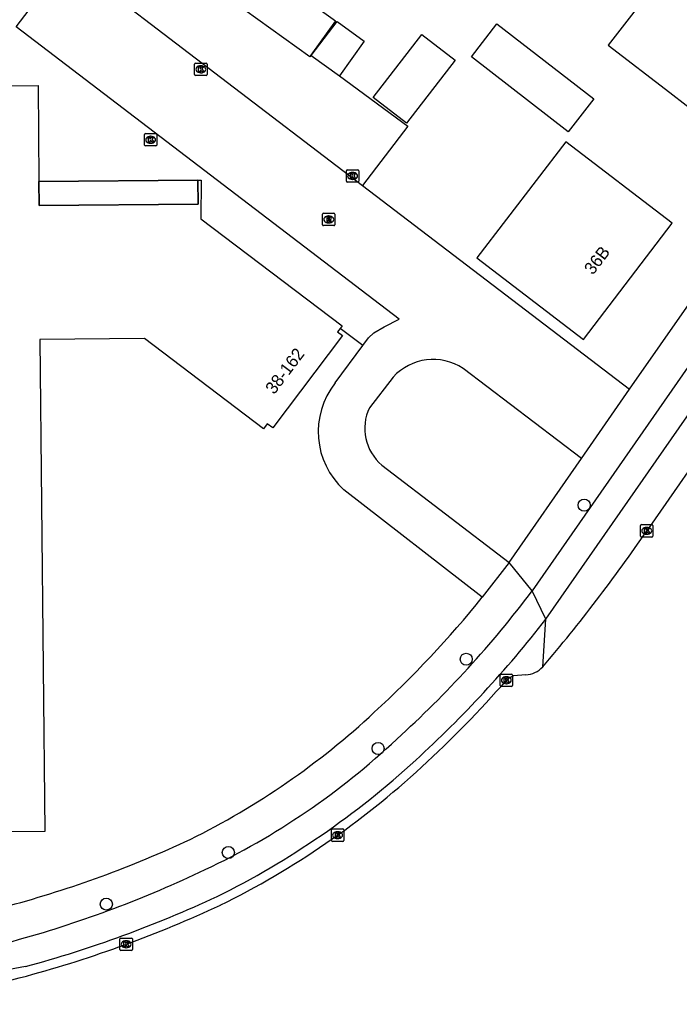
# Model space of a CAD drawing. Extents: x 160158 to 160921, y 381517 to 382041.
# Drawn here: x 160584.1 to 160637.4, y 381547.2 to 381626.4 of the extents above; entities that cross this region are included whole.
import ezdxf

# ---------------------------------------------------------------- set-up
doc = ezdxf.new("R2010")
doc.units = 0
for name, color, linetype in [('IMGEO_Berm_open', 7, 'Continuous'), ('IMGEO_Boom', 7, 'Continuous'), ('IMGEO_Fietspad_open', 7, 'Continuous'), ('IMGEO_Kolk', 7, 'Continuous'), ('IMGEO_Pand', 7, 'Continuous'), ('IMGEO_Pand_nummerreeks', 7, 'Continuous'), ('IMGEO_Pand_overbouw', 7, 'Continuous'), ('IMGEO_Parkeervlak_open', 7, 'Continuous'), ('IMGEO_Rijbaan_lokaal_gesloten', 7, 'Continuous'), ('IMGEO_Rijbaan_lokaal_open', 7, 'Continuous'), ('IMGEO_Rioolput', 7, 'Continuous'), ('IMGEO_Voetpad_open', 7, 'Continuous')]:
    doc.layers.add(name, color=color, linetype=linetype)

msp = doc.modelspace()

# ---------------------------------------------------------------- linework, layer by layer
at = {"layer": 'IMGEO_Berm_open'}
msp.add_lwpolyline([(160626.346, 381574.092), (160626.609, 381577.958)], dxfattribs=at)
at = {"layer": 'IMGEO_Boom'}
for centre in [(160629.691, 381587.166), (160620.166, 381574.712), (160613.04, 381567.494), (160600.942, 381559.087), (160591.077, 381554.92)]:
    msp.add_circle(centre, 0.489, dxfattribs=at)
at = {"layer": 'IMGEO_Fietspad_open'}
for points in [[(160658.078, 381626.982), (160657.224, 381625.75), (160654.545, 381621.952), (160652.131, 381618.546), (160625.5, 381580.252)], [(160626.609, 381577.958), (160653.548, 381616.624), (160658.001, 381622.958)], [(160626.609, 381577.958), (160625.5, 381580.252)], [(160584.546, 381549.868), (160573.856, 381547.875), (160569.741, 381547.684)]]:
    msp.add_lwpolyline(points, dxfattribs=at)
for centre, radius, start, end in [((160558.076, 381630.831), 84.287, 312.06612, 323.12406), ((160554.773, 381633.721), 90.939, 312.39102, 322.17935), ((160573.524, 381611.804), 59.825, 295.27447, 313.29148), ((160568.779, 381618.18), 70.019, 296.5051, 312.49983), ((160559.234, 381641.019), 92.346, 285.6024, 295.55323), ((160558.323, 381645.705), 99.36, 285.30275, 294.81732), ((160569.083, 381603.441), 53.507, 273.98019, 286.26704)]:
    msp.add_arc(centre, radius, start, end, dxfattribs=at)
at = {"layer": 'IMGEO_Kolk'}
for p, q in [((160598.215, 381621.98), (160598.215, 381622.832)), ((160598.29, 381622.906), (160599.142, 381622.906)), ((160599.216, 381622.832), (160599.216, 381621.98)), ((160598.726, 381622.126), (160598.701, 381622.126)), ((160598.703, 381622.686), (160598.728, 381622.686)), ((160599.142, 381621.906), (160598.29, 381621.906)), ((160594.161, 381616.286), (160594.161, 381617.138)), ((160594.236, 381617.212), (160595.088, 381617.212)), ((160594.649, 381616.992), (160594.674, 381616.992)), ((160595.162, 381617.138), (160595.162, 381616.286)), ((160595.088, 381616.212), (160594.236, 381616.212)), ((160594.672, 381616.432), (160594.647, 381616.432)), ((160610.479, 381613.358), (160610.479, 381614.21)), ((160610.554, 381614.284), (160611.406, 381614.284)), ((160611.48, 381614.21), (160611.48, 381613.358)), ((160610.99, 381613.504), (160610.965, 381613.504)), ((160610.967, 381614.064), (160610.992, 381614.064)), ((160611.406, 381613.284), (160610.554, 381613.284)), ((160634.325, 381585.596), (160635.177, 381585.596)), ((160634.25, 381584.67), (160634.25, 381585.522)), ((160634.761, 381584.816), (160634.736, 381584.816)), ((160634.738, 381585.376), (160634.763, 381585.376)), ((160635.251, 381585.522), (160635.251, 381584.67)), ((160635.177, 381584.596), (160634.325, 381584.596)), ((160622.906, 381572.585), (160622.906, 381573.437)), ((160622.981, 381573.511), (160623.833, 381573.511)), ((160623.394, 381573.291), (160623.419, 381573.291)), ((160623.907, 381573.437), (160623.907, 381572.585)), ((160623.833, 381572.511), (160622.981, 381572.511)), ((160623.417, 381572.731), (160623.392, 381572.731)), ((160609.27, 381560.066), (160609.27, 381560.918)), ((160609.345, 381560.992), (160610.197, 381560.992)), ((160609.758, 381560.772), (160609.783, 381560.772)), ((160610.271, 381560.918), (160610.271, 381560.066)), ((160610.197, 381559.992), (160609.345, 381559.992)), ((160609.781, 381560.212), (160609.756, 381560.212)), ((160592.183, 381551.246), (160592.183, 381552.098)), ((160592.258, 381552.172), (160593.11, 381552.172)), ((160592.671, 381551.952), (160592.696, 381551.952)), ((160593.184, 381552.098), (160593.184, 381551.246)), ((160593.11, 381551.172), (160592.258, 381551.172)), ((160592.694, 381551.392), (160592.669, 381551.392))]:
    msp.add_line(p, q, dxfattribs=at)
for points in [[(160598.215, 381621.98), (160598.215, 381622.832)], [(160598.29, 381622.906), (160599.142, 381622.906)], [(160599.216, 381622.832), (160599.216, 381621.98)], [(160598.536, 381622.606), (160598.659, 381622.606), (160598.659, 381622.455), (160598.789, 381622.606), (160598.953, 381622.606), (160598.807, 381622.455), (160598.96, 381622.206), (160598.808, 381622.206), (160598.723, 381622.37), (160598.659, 381622.303), (160598.659, 381622.206), (160598.536, 381622.206), (160598.536, 381622.606)], [(160599.142, 381621.906), (160598.29, 381621.906)], [(160594.161, 381616.286), (160594.161, 381617.138)], [(160594.236, 381617.212), (160595.088, 381617.212)], [(160594.482, 381616.912), (160594.605, 381616.912), (160594.605, 381616.761), (160594.735, 381616.912), (160594.899, 381616.912), (160594.753, 381616.761), (160594.906, 381616.512), (160594.754, 381616.512), (160594.669, 381616.676), (160594.605, 381616.609), (160594.605, 381616.512), (160594.482, 381616.512), (160594.482, 381616.912)], [(160595.162, 381617.138), (160595.162, 381616.286)], [(160595.088, 381616.212), (160594.236, 381616.212)], [(160610.479, 381613.358), (160610.479, 381614.21)], [(160610.554, 381614.284), (160611.406, 381614.284)], [(160611.48, 381614.21), (160611.48, 381613.358)], [(160610.8, 381613.984), (160610.923, 381613.984), (160610.923, 381613.833), (160611.053, 381613.984), (160611.217, 381613.984), (160611.071, 381613.833), (160611.224, 381613.584), (160611.072, 381613.584), (160610.987, 381613.748), (160610.923, 381613.681), (160610.923, 381613.584), (160610.8, 381613.584), (160610.8, 381613.984)], [(160611.406, 381613.284), (160610.554, 381613.284)], [(160634.325, 381585.596), (160635.177, 381585.596)], [(160634.25, 381584.67), (160634.25, 381585.522)], [(160634.571, 381585.296), (160634.694, 381585.296), (160634.694, 381585.145), (160634.824, 381585.296), (160634.988, 381585.296), (160634.842, 381585.145), (160634.995, 381584.896), (160634.843, 381584.896), (160634.758, 381585.06), (160634.694, 381584.993), (160634.694, 381584.896), (160634.571, 381584.896), (160634.571, 381585.296)], [(160635.251, 381585.522), (160635.251, 381584.67)], [(160635.177, 381584.596), (160634.325, 381584.596)], [(160622.906, 381572.585), (160622.906, 381573.437)], [(160622.981, 381573.511), (160623.833, 381573.511)], [(160623.227, 381573.211), (160623.35, 381573.211), (160623.35, 381573.06), (160623.48, 381573.211), (160623.644, 381573.211), (160623.498, 381573.06), (160623.651, 381572.811), (160623.499, 381572.811), (160623.414, 381572.975), (160623.35, 381572.908), (160623.35, 381572.811), (160623.227, 381572.811), (160623.227, 381573.211)], [(160623.907, 381573.437), (160623.907, 381572.585)], [(160623.833, 381572.511), (160622.981, 381572.511)], [(160609.27, 381560.066), (160609.27, 381560.918)], [(160609.345, 381560.992), (160610.197, 381560.992)], [(160609.591, 381560.692), (160609.714, 381560.692), (160609.714, 381560.541), (160609.844, 381560.692), (160610.008, 381560.692), (160609.862, 381560.541), (160610.015, 381560.292), (160609.863, 381560.292), (160609.778, 381560.456), (160609.714, 381560.389), (160609.714, 381560.292), (160609.591, 381560.292), (160609.591, 381560.692)], [(160610.271, 381560.918), (160610.271, 381560.066)], [(160610.197, 381559.992), (160609.345, 381559.992)], [(160592.183, 381551.246), (160592.183, 381552.098)], [(160592.258, 381552.172), (160593.11, 381552.172)], [(160592.504, 381551.872), (160592.627, 381551.872), (160592.627, 381551.721), (160592.757, 381551.872), (160592.921, 381551.872), (160592.775, 381551.721), (160592.928, 381551.472), (160592.776, 381551.472), (160592.691, 381551.636), (160592.627, 381551.569), (160592.627, 381551.472), (160592.504, 381551.472), (160592.504, 381551.872)], [(160593.184, 381552.098), (160593.184, 381551.246)], [(160593.11, 381551.172), (160592.258, 381551.172)]]:
    msp.add_lwpolyline(points, dxfattribs=at)
for centre, start, end in [((160598.292, 381622.83), 91.55205, 178.44795), ((160598.292, 381622.83), 91.55205, 178.44795), ((160599.14, 381622.83), 1.55205, 88.44795), ((160599.14, 381622.83), 1.55205, 88.44795), ((160598.292, 381621.982), 181.55205, 268.44795), ((160598.292, 381621.982), 181.55205, 268.44795), ((160599.14, 381621.982), 271.55205, 358.44795), ((160599.14, 381621.982), 271.55205, 358.44795), ((160594.238, 381617.136), 91.55205, 178.44795), ((160594.238, 381617.136), 91.55205, 178.44795), ((160595.086, 381617.136), 1.55205, 88.44795), ((160595.086, 381617.136), 1.55205, 88.44795), ((160594.238, 381616.288), 181.55205, 268.44795), ((160594.238, 381616.288), 181.55205, 268.44795), ((160595.086, 381616.288), 271.55205, 358.44795), ((160595.086, 381616.288), 271.55205, 358.44795), ((160610.556, 381614.208), 91.55205, 178.44795), ((160610.556, 381614.208), 91.55205, 178.44795), ((160611.404, 381614.208), 1.55205, 88.44795), ((160611.404, 381614.208), 1.55205, 88.44795), ((160610.556, 381613.36), 181.55205, 268.44795), ((160610.556, 381613.36), 181.55205, 268.44795), ((160611.404, 381613.36), 271.55205, 358.44795), ((160611.404, 381613.36), 271.55205, 358.44795), ((160634.327, 381585.52), 91.55205, 178.44795), ((160634.327, 381585.52), 91.55205, 178.44795), ((160635.175, 381585.52), 1.55205, 88.44795), ((160635.175, 381585.52), 1.55205, 88.44795), ((160634.327, 381584.672), 181.55205, 268.44795), ((160634.327, 381584.672), 181.55205, 268.44795), ((160635.175, 381584.672), 271.55205, 358.44795), ((160635.175, 381584.672), 271.55205, 358.44795), ((160622.983, 381573.435), 91.55205, 178.44795), ((160622.983, 381573.435), 91.55205, 178.44795), ((160623.831, 381573.435), 1.55205, 88.44795), ((160623.831, 381573.435), 1.55205, 88.44795), ((160622.983, 381572.587), 181.55205, 268.44795), ((160622.983, 381572.587), 181.55205, 268.44795), ((160623.831, 381572.587), 271.55205, 358.44795), ((160623.831, 381572.587), 271.55205, 358.44795), ((160609.347, 381560.916), 91.55205, 178.44795), ((160609.347, 381560.916), 91.55205, 178.44795), ((160610.195, 381560.916), 1.55205, 88.44795), ((160610.195, 381560.916), 1.55205, 88.44795), ((160609.347, 381560.068), 181.55205, 268.44795), ((160609.347, 381560.068), 181.55205, 268.44795), ((160610.195, 381560.068), 271.55205, 358.44795), ((160610.195, 381560.068), 271.55205, 358.44795), ((160592.26, 381552.096), 91.55205, 178.44795), ((160592.26, 381552.096), 91.55205, 178.44795), ((160593.108, 381552.096), 1.55205, 88.44795), ((160593.108, 381552.096), 1.55205, 88.44795), ((160592.26, 381551.248), 181.55205, 268.44795), ((160592.26, 381551.248), 181.55205, 268.44795), ((160593.108, 381551.248), 271.55205, 358.44795), ((160593.108, 381551.248), 271.55205, 358.44795)]:
    msp.add_arc(centre, 0.0765, start, end, dxfattribs=at)
for centre, major_axis, ratio, start_param, end_param in [((160598.702, 381622.406), (-0.387, 0.002), 0.722429, 4.712389, 7.853982), ((160598.727, 381622.406), (-0.39, 0.002), 0.717154, 1.570796, 4.712389), ((160594.648, 381616.712), (-0.387, 0.002), 0.722429, 4.712389, 7.853982), ((160594.673, 381616.712), (-0.39, 0.002), 0.717154, 1.570796, 4.712389), ((160610.966, 381613.784), (-0.387, 0.002), 0.722429, 4.712389, 7.853982), ((160610.991, 381613.784), (-0.39, 0.002), 0.717154, 1.570796, 4.712389), ((160634.737, 381585.096), (-0.387, 0.002), 0.722429, 4.712389, 7.853982), ((160634.762, 381585.096), (-0.39, 0.002), 0.717154, 1.570796, 4.712389), ((160623.393, 381573.011), (-0.387, 0.002), 0.722429, 4.712389, 7.853982), ((160623.418, 381573.011), (-0.39, 0.002), 0.717154, 1.570796, 4.712389), ((160609.757, 381560.492), (-0.387, 0.002), 0.722429, 4.712389, 7.853982), ((160609.782, 381560.492), (-0.39, 0.002), 0.717154, 1.570796, 4.712389), ((160592.67, 381551.672), (-0.387, 0.002), 0.722429, 4.712389, 7.853982), ((160592.695, 381551.672), (-0.39, 0.002), 0.717154, 1.570796, 4.712389)]:
    msp.add_ellipse(centre, major_axis=major_axis, ratio=ratio, start_param=start_param, end_param=end_param, dxfattribs=at)
at = {"layer": 'IMGEO_Pand'}
for points in [[(160636.053, 381630.085), (160631.637, 381624.368), (160636.619, 381620.52), (160640.576, 381617.464), (160647.232, 381626.081), (160639.436, 381632.103)], [(160604.359, 381630.089), (160609.609, 381626.314), (160607.615, 381623.541)], [(160607.615, 381623.541), (160607.526, 381623.417), (160602.276, 381627.192), (160602.357, 381627.305)], [(160607.624, 381623.535), (160609.734, 381626.268), (160611.928, 381624.691), (160609.914, 381621.889)], [(160630.465, 381620.012), (160628.398, 381617.346), (160620.579, 381623.406), (160622.646, 381626.072), (160630.465, 381620.012)], [(160619.261, 381623.147), (160615.325, 381618.052), (160612.65, 381620.118), (160616.585, 381625.214), (160619.261, 381623.147)], [(160607.624, 381623.535), (160609.914, 381621.889)], [(160609.979, 381601.448), (160609.769, 381601.17), (160610.162, 381600.874), (160604.524, 381593.418), (160604.088, 381593.748), (160603.785, 381593.347), (160594.153, 381600.631), (160585.715, 381600.557), (160586.116, 381560.796), (160572.564, 381560.678), (160572.228, 381599.143), (160573.491, 381599.154), (160573.451, 381603.696), (160552.72, 381603.514), (160552.569, 381620.809), (160576.509, 381621.016)], [(160576.509, 381621.016), (160585.561, 381621.094), (160585.629, 381613.324)], [(160629.64, 381600.577), (160636.816, 381609.978), (160628.201, 381616.555), (160621.024, 381607.154), (160629.64, 381600.577)], [(160598.485, 381613.435), (160598.502, 381611.516), (160585.646, 381611.404), (160585.629, 381613.324)], [(160598.485, 381613.435), (160598.747, 381613.437), (160598.72, 381610.313), (160610.148, 381601.671), (160609.979, 381601.448)]]:
    msp.add_lwpolyline(points, dxfattribs=at)
at = {"layer": 'IMGEO_Pand_overbouw'}
msp.add_lwpolyline([(160598.485, 381613.435), (160585.629, 381613.324), (160585.646, 381611.404), (160598.502, 381611.516)], close=True, dxfattribs=at)
at = {"layer": 'IMGEO_Parkeervlak_open'}
for points in [[(160607.615, 381623.541), (160607.624, 381623.535)], [(160609.914, 381621.889), (160615.436, 381617.81), (160611.789, 381613.027)], [(160611.822, 381600.089), (160609.979, 381601.448)]]:
    msp.add_lwpolyline(points, dxfattribs=at)
at = {"layer": 'IMGEO_Rijbaan_lokaal_gesloten'}
for points in [[(160640.703, 381593.658), (160634.753, 381585.096)], [(160624.971, 381573.447), (160623.974, 381573.368), (160623.608, 381573.179), (160623.408, 381573.009)]]:
    msp.add_lwpolyline(points, dxfattribs=at)
for centre, radius, start, end in [((160525.274, 381660.024), 132.665, 319.62864, 325.61207), ((160624.804, 381575.592), 2.152, 274.46349, 315.7982), ((160555.56, 381632.409), 90.176, 312.57532, 318.79865), ((160569.574, 381617.004), 69.351, 296.292, 312.65928), ((160558.927, 381643.751), 98.073, 285.19301, 294.94756), ((160565.577, 381620.396), 73.793, 277.37696, 284.96204)]:
    msp.add_arc(centre, radius, start, end, dxfattribs=at)
at = {"layer": 'IMGEO_Rijbaan_lokaal_open'}
for points in [[(160611.822, 381600.089), (160612.269, 381600.706), (160612.703, 381601.092), (160613.524, 381601.59), (160614.738, 381602.216), (160583.784, 381625.843), (160587.913, 381631.252), (160611.789, 381613.027)], [(160611.789, 381613.027), (160633.366, 381596.557)], [(160609.581, 381597.049), (160611.822, 381600.089)], [(160614.258, 381597.522), (160612.335, 381595.05)], [(160629.491, 381590.946), (160619.908, 381598.227)], [(160629.491, 381590.946), (160633.366, 381596.557)], [(160613.342, 381590.405), (160623.64, 381582.543)], [(160621.462, 381579.722), (160610.286, 381588.409)], [(160623.64, 381582.543), (160621.462, 381579.722)]]:
    msp.add_lwpolyline(points, dxfattribs=at)
for centre, radius, start, end in [((160617.495, 381594.576), 4.376, 56.5318, 137.69327), ((160614.533, 381593.104), 6.331, 141.46196, 227.86772), ((160615.874, 381593.386), 3.911, 154.81537, 229.64862)]:
    msp.add_arc(centre, radius, start, end, dxfattribs=at)
at = {"layer": 'IMGEO_Rioolput'}
for p, q in [((160608.551, 381609.844), (160608.551, 381610.696)), ((160608.626, 381610.77), (160609.478, 381610.77)), ((160609.039, 381610.55), (160609.064, 381610.55)), ((160609.552, 381610.696), (160609.552, 381609.844)), ((160609.478, 381609.77), (160608.626, 381609.77)), ((160609.062, 381609.99), (160609.037, 381609.99))]:
    msp.add_line(p, q, dxfattribs=at)
for points in [[(160608.551, 381609.844), (160608.551, 381610.696)], [(160608.626, 381610.77), (160609.478, 381610.77)], [(160609.14, 381610.468), (160608.888, 381610.47), (160608.888, 381610.07)], [(160608.888, 381610.07), (160609.012, 381610.07), (160609.012, 381610.232), (160609.023, 381610.232)], [(160609.066, 381610.389), (160609.012, 381610.389), (160609.012, 381610.308)], [(160609.012, 381610.308), (160609.064, 381610.308)], [(160609.07, 381610.203), (160609.141, 381610.07), (160609.281, 381610.07), (160609.216, 381610.196)], [(160609.552, 381610.696), (160609.552, 381609.844)], [(160609.478, 381609.77), (160608.626, 381609.77)]]:
    msp.add_lwpolyline(points, dxfattribs=at)
for centre, radius, start, end in [((160608.628, 381610.694), 0.0765, 91.55205, 178.44795), ((160608.628, 381610.694), 0.0765, 91.55205, 178.44795), ((160609.022, 381610.179), 0.0533, 26.02933, 88.69889), ((160609.048, 381610.497), 0.19, 274.7715, 282.96867), ((160609.072, 381610.293), 0.0964, 77.00612, 93.18647), ((160609.086, 381610.35), 0.0378, 276.66336, 79.67722), ((160609.139, 381610.358), 0.109, 350.36119, 89.41601), ((160609.137, 381610.358), 0.112, 277.58423, 350.98172), ((160609.121, 381610.143), 0.108, 29.51342, 73.79051), ((160609.476, 381610.694), 0.0765, 1.55205, 88.44795), ((160609.476, 381610.694), 0.0765, 1.55205, 88.44795), ((160608.628, 381609.846), 0.0765, 181.55205, 268.44795), ((160608.628, 381609.846), 0.0765, 181.55205, 268.44795), ((160609.476, 381609.846), 0.0765, 271.55205, 358.44795), ((160609.476, 381609.846), 0.0765, 271.55205, 358.44795)]:
    msp.add_arc(centre, radius, start, end, dxfattribs=at)
for centre, major_axis, ratio, start_param, end_param in [((160609.038, 381610.27), (-0.387, 0.002), 0.722429, 4.712389, 7.853982), ((160609.063, 381610.27), (-0.39, 0.002), 0.717154, 1.570796, 4.712389)]:
    msp.add_ellipse(centre, major_axis=major_axis, ratio=ratio, start_param=start_param, end_param=end_param, dxfattribs=at)
at = {"layer": 'IMGEO_Voetpad_open'}
for points in [[(160633.366, 381596.557), (160641.062, 381607.564), (160653.405, 381625.283)], [(160585.629, 381613.324), (160598.485, 381613.435)], [(160623.64, 381582.543), (160629.491, 381590.946)], [(160625.5, 381580.252), (160623.64, 381582.543)]]:
    msp.add_lwpolyline(points, dxfattribs=at)
for centre, radius, start, end in [((160553.907, 381634.378), 86.896, 312.61072, 321.02508), ((160570.144, 381616.174), 62.507, 296.31656, 312.95434), ((160559.651, 381641.913), 90.252, 285.15257, 295.04329)]:
    msp.add_arc(centre, radius, start, end, dxfattribs=at)

# ---------------------------------------------------------------- texts
at = {"layer": 'IMGEO_Pand_nummerreeks'}
for s, rotation, p in [('36B', 52.64467, (160630.402, 381605.728)), ('38-162', 52.90692, (160604.644, 381596.063))]:
    msp.add_text(s, height=1, rotation=rotation, dxfattribs=at).set_placement(p)

doc.saveas('drawing.dxf')
